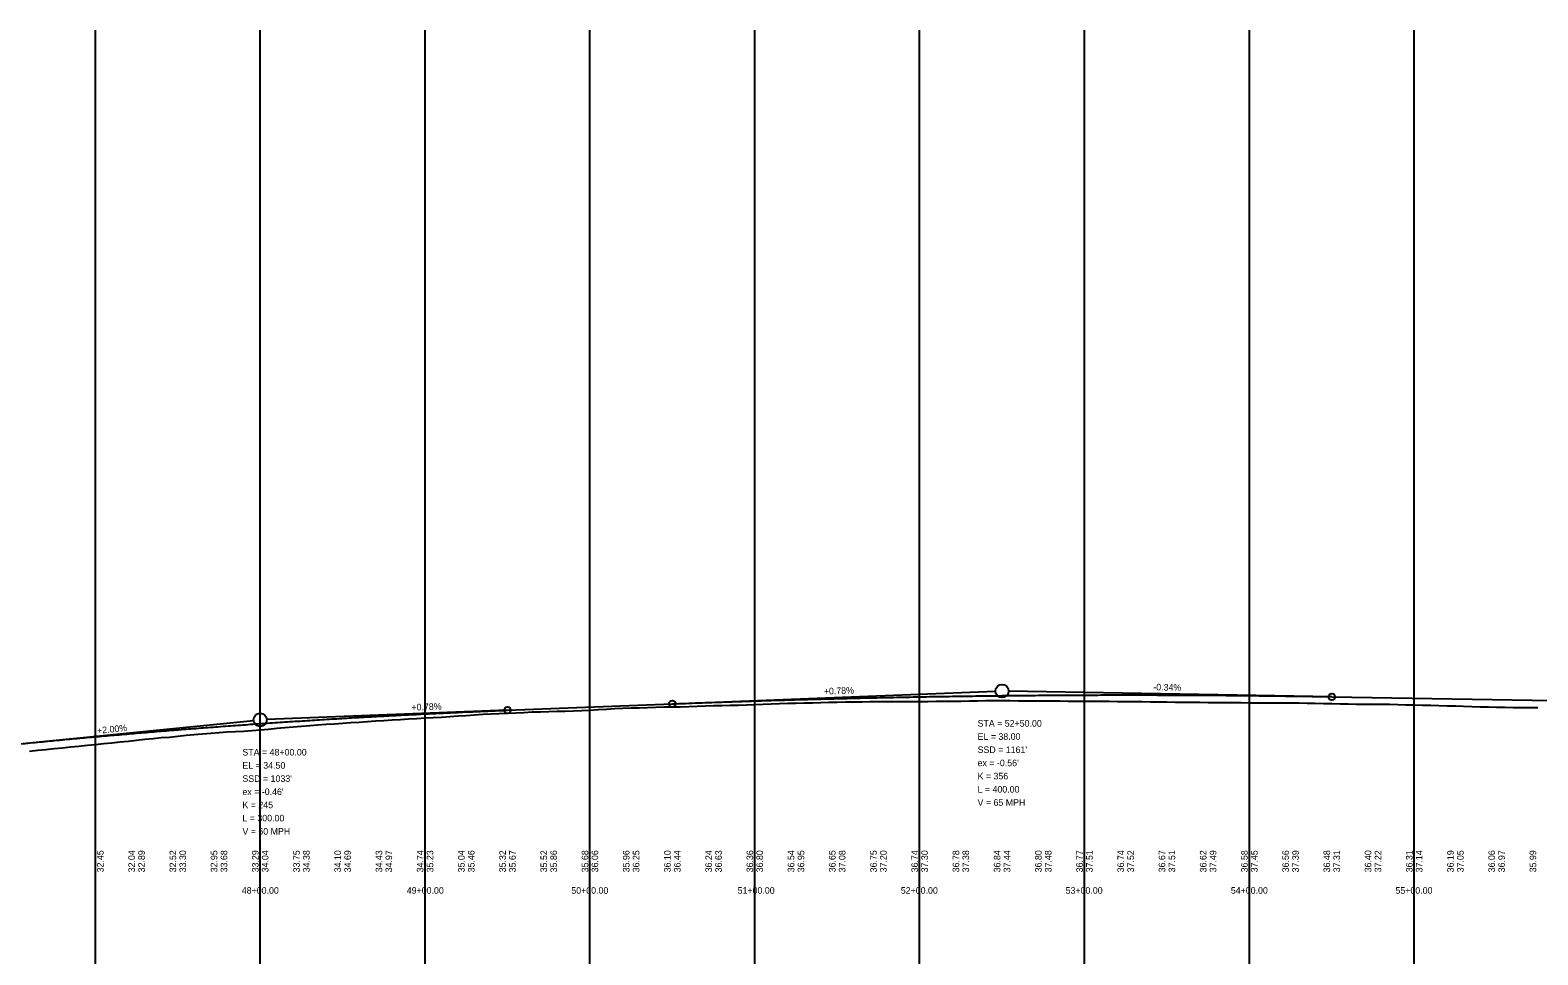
# Model space of a CAD drawing. Extents: x 3880794 to 3915434, y 287517 to 300173.
# Drawn here: x 3903812 to 3904726, y 292943 to 293504 of the extents above; entities that cross this region are included whole.
import ezdxf

# ---------------------------------------------------------------- set-up
doc = ezdxf.new("R2010")
doc.units = 0
for name, color, linetype in [('Level 1', 7, 'Continuous'), ('Level 2', 7, 'Continuous'), ('Level 30', 7, 'Continuous'), ('Level 32', 7, 'Continuous')]:
    doc.layers.add(name, color=color, linetype=linetype)

msp = doc.modelspace()

# ---------------------------------------------------------------- linework, layer by layer
at = {"layer": 'Level 1'}
for p, q in [((3903851.21, 292476.49), (3903851.21, 293504.13)), ((3903951.21, 292476.49), (3903951.21, 293504.13)), ((3904051.21, 292476.49), (3904051.21, 293504.13)), ((3904151.21, 292476.49), (3904151.21, 293504.13)), ((3904251.21, 292476.49), (3904251.21, 293504.13)), ((3904351.21, 292476.49), (3904351.21, 293504.13)), ((3904451.21, 292476.49), (3904451.21, 293504.13)), ((3904551.21, 292476.49), (3904551.21, 293504.13)), ((3904651.21, 292476.49), (3904651.21, 293504.13))]:
    msp.add_line(p, q, dxfattribs=at)
at = {"layer": 'Level 2'}
for p, q in [((3904201.21, 293095.38), (3904397.22, 293103)), ((3904601.21, 293099.71), (3904405.21, 293103.09)), ((3904601.21, 293099.71), (3904876.21, 293094.97)), ((3904101.21, 293091.49), (3903955.21, 293085.81)), ((3904101.21, 293091.49), (3904201.21, 293095.38)), ((3903801.21, 293070.66), (3903947.23, 293085.26))]:
    msp.add_line(p, q, dxfattribs=at)
for points in [[(3903811.21, 293066.74), (3903816.21, 293067.22), (3903821.21, 293067.75), (3903826.21, 293068.27), (3903831.21, 293068.77), (3903836.21, 293069.27), (3903841.21, 293069.77), (3903846.21, 293070.28), (3903851.21, 293070.8), (3903856.21, 293071.31), (3903861.21, 293071.82), (3903866.21, 293072.32), (3903871.21, 293072.83), (3903876.21, 293073.35), (3903881.21, 293073.87), (3903886.21, 293074.39), (3903891.21, 293074.9), (3903896.21, 293075.24), (3903901.21, 293075.75), (3903906.21, 293076.29), (3903911.21, 293076.79), (3903916.21, 293077.15), (3903921.21, 293077.53), (3903926.21, 293077.91), (3903931.21, 293078.39), (3903936.21, 293078.61), (3903941.21, 293078.84), (3903946.21, 293079.14), (3903951.21, 293079.62), (3903956.21, 293080.11), (3903961.21, 293080.72), (3903966.21, 293081.12), (3903971.21, 293081.51), (3903976.21, 293081.89), (3903981.21, 293082.25), (3903986.21, 293082.61), (3903991.21, 293082.96), (3903996.21, 293083.32), (3904001.21, 293083.66), (3904006.21, 293084.02), (3904011.21, 293084.35), (3904016.21, 293084.67), (3904021.21, 293084.99), (3904026.21, 293085.32), (3904031.21, 293085.65), (3904036.21, 293085.96), (3904041.21, 293086.27), (3904046.21, 293086.58), (3904051.21, 293086.88), (3904056.21, 293087.16), (3904061.21, 293087.38), (3904066.21, 293087.69), (3904071.21, 293088.03), (3904076.21, 293088.36), (3904081.21, 293088.69), (3904086.21, 293089.02), (3904091.21, 293089.26), (3904096.21, 293089.52), (3904101.21, 293089.76), (3904106.21, 293090), (3904111.21, 293090.23), (3904116.21, 293090.44), (3904121.21, 293090.6), (3904126.21, 293090.74), (3904131.21, 293090.88), (3904136.21, 293091.02), (3904141.21, 293091.17), (3904146.21, 293091.28), (3904151.21, 293091.58)], [(3904151.21, 293091.58), (3904156.21, 293092), (3904161.21, 293092.25), (3904166.21, 293092.51), (3904171.21, 293092.75), (3904176.21, 293092.95), (3904181.21, 293093.01), (3904186.21, 293093.16), (3904191.21, 293093.32), (3904196.21, 293093.49), (3904201.21, 293093.64), (3904206.21, 293093.64), (3904211.21, 293093.68), (3904216.21, 293093.93), (3904221.21, 293094.13), (3904226.21, 293094.35), (3904231.21, 293094.46), (3904236.21, 293094.53), (3904241.21, 293094.54), (3904246.21, 293094.7), (3904251.21, 293094.95), (3904256.21, 293095.19), (3904261.21, 293095.42), (3904266.21, 293095.66), (3904271.21, 293095.72), (3904276.21, 293095.83), (3904281.21, 293095.95), (3904286.21, 293096.06), (3904291.21, 293096.17), (3904296.21, 293096.32), (3904301.21, 293096.41), (3904306.21, 293096.5), (3904311.21, 293096.58), (3904316.21, 293096.66), (3904321.21, 293096.77), (3904326.21, 293096.9), (3904331.21, 293096.88), (3904336.21, 293096.86), (3904341.21, 293096.83), (3904346.21, 293096.8), (3904351.21, 293096.86), (3904356.21, 293096.9), (3904361.21, 293096.94), (3904366.21, 293096.97), (3904371.21, 293097), (3904376.21, 293097.07), (3904381.21, 293097.16), (3904386.21, 293097.23), (3904391.21, 293097.31), (3904396.21, 293097.36), (3904401.21, 293097.36), (3904406.21, 293097.33), (3904411.21, 293097.29), (3904416.21, 293097.25), (3904421.21, 293097.2), (3904426.21, 293097.15), (3904431.21, 293097.13), (3904436.21, 293097.12), (3904441.21, 293097.1), (3904446.21, 293097.07), (3904451.21, 293097.02), (3904456.21, 293097.01), (3904461.21, 293096.99), (3904466.21, 293096.98), (3904471.21, 293096.89), (3904476.21, 293096.84), (3904481.21, 293096.78), (3904486.21, 293096.72), (3904491.21, 293096.65), (3904496.21, 293096.59), (3904501.21, 293096.53), (3904506.21, 293096.47), (3904511.21, 293096.41), (3904516.21, 293096.35), (3904521.21, 293096.31), (3904526.21, 293096.26), (3904531.21, 293096.21), (3904536.21, 293096.17), (3904541.21, 293096.12), (3904546.21, 293096.11), (3904551.21, 293096.07), (3904556.21, 293096.02), (3904561.21, 293095.97), (3904566.21, 293096.01), (3904571.21, 293095.98), (3904576.21, 293095.95), (3904581.21, 293095.92), (3904586.21, 293095.89), (3904591.21, 293095.84), (3904596.21, 293095.66), (3904601.21, 293095.53), (3904606.21, 293095.41), (3904611.21, 293095.29), (3904616.21, 293095.25), (3904621.21, 293095.21), (3904626.21, 293095.17), (3904631.21, 293095.14), (3904636.21, 293095.1), (3904641.21, 293095), (3904646.21, 293094.87), (3904651.21, 293094.73)], [(3904651.21, 293094.73), (3904656.21, 293094.6), (3904661.21, 293094.53), (3904666.21, 293094.41), (3904671.21, 293094.26), (3904676.21, 293094.1), (3904681.21, 293093.95), (3904686.21, 293093.79), (3904691.21, 293093.64), (3904696.21, 293093.53), (3904701.21, 293093.43), (3904706.21, 293093.34), (3904711.21, 293093.25), (3904716.21, 293093.22), (3904721.21, 293093.16), (3904726.21, 293093.13)]]:
    msp.add_lwpolyline(points, dxfattribs=at)
for centre, radius in [((3904401.21, 293103.16), 4), ((3904601.21, 293099.71), 2), ((3904101.21, 293091.49), 2), ((3904201.21, 293095.38), 2), ((3903951.21, 293085.66), 4)]:
    msp.add_circle(centre, radius, dxfattribs=at)
for points in [[(3904201.21, 293095.38), (3904209.21, 293095.69), (3904217.21, 293095.98), (3904225.21, 293096.27), (3904233.21, 293096.55), (3904241.21, 293096.82), (3904249.21, 293097.09), (3904257.21, 293097.34), (3904265.21, 293097.58), (3904273.21, 293097.82), (3904281.21, 293098.04), (3904289.21, 293098.26), (3904297.21, 293098.47), (3904305.21, 293098.67), (3904313.21, 293098.86), (3904321.21, 293099.04), (3904329.21, 293099.21), (3904337.21, 293099.37), (3904345.21, 293099.53), (3904353.21, 293099.67), (3904361.21, 293099.81), (3904369.21, 293099.93), (3904377.21, 293100.05), (3904385.21, 293100.16), (3904393.21, 293100.26), (3904401.21, 293100.35), (3904409.21, 293100.43), (3904417.21, 293100.51), (3904425.21, 293100.57), (3904433.21, 293100.63), (3904441.21, 293100.67), (3904449.21, 293100.71), (3904457.21, 293100.74), (3904465.21, 293100.76), (3904473.21, 293100.77), (3904481.21, 293100.77), (3904489.21, 293100.76), (3904497.21, 293100.74), (3904505.21, 293100.72), (3904513.21, 293100.68), (3904521.21, 293100.64), (3904529.21, 293100.59), (3904537.21, 293100.53), (3904545.21, 293100.46), (3904553.21, 293100.38), (3904561.21, 293100.29), (3904569.21, 293100.19), (3904577.21, 293100.08), (3904585.21, 293099.97), (3904593.21, 293099.84), (3904601.21, 293099.71)], [(3903801.21, 293070.66), (3903807.21, 293071.25), (3903813.21, 293071.84), (3903819.21, 293072.42), (3903825.21, 293073), (3903831.21, 293073.57), (3903837.21, 293074.13), (3903843.21, 293074.68), (3903849.21, 293075.22), (3903855.21, 293075.76), (3903861.21, 293076.29), (3903867.21, 293076.81), (3903873.21, 293077.33), (3903879.21, 293077.84), (3903885.21, 293078.34), (3903891.21, 293078.83), (3903897.21, 293079.32), (3903903.21, 293079.8), (3903909.21, 293080.27), (3903915.21, 293080.73), (3903921.21, 293081.19), (3903927.21, 293081.64), (3903933.21, 293082.08), (3903939.21, 293082.52), (3903945.21, 293082.95), (3903951.21, 293083.37), (3903957.21, 293083.78), (3903963.21, 293084.18), (3903969.21, 293084.58), (3903975.21, 293084.97), (3903981.21, 293085.36), (3903987.21, 293085.73), (3903993.21, 293086.1), (3903999.21, 293086.46), (3904005.21, 293086.82), (3904011.21, 293087.17), (3904017.21, 293087.51), (3904023.21, 293087.84), (3904029.21, 293088.16), (3904035.21, 293088.48), (3904041.21, 293088.79), (3904047.21, 293089.09), (3904053.21, 293089.39), (3904059.21, 293089.68), (3904065.21, 293089.96), (3904071.21, 293090.23), (3904077.21, 293090.5), (3904083.21, 293090.76), (3904089.21, 293091.01), (3904095.21, 293091.25), (3904101.21, 293091.49)]]:
    msp.add_spline(points, degree=3, dxfattribs=at)

# ---------------------------------------------------------------- texts
for s, rotation, p in [('+0.78%', 2.22705, (3904293.15, 293100.96)), ('-0.34%', 359.01224, (3904492.92, 293103.58)), ('+0.78%', 2.22705, (3904043, 293091.23)), ('+2.00%', 5.71059, (3903852.45, 293077.12))]:
    msp.add_text(s, height=4, rotation=rotation, dxfattribs=at).set_placement(p)
for s, p in [('STA = 52+50.00', (3904386.35, 293081.54)), ('EL = 38.00', (3904386.35, 293073.54)), ('STA = 48+00.00', (3903940.41, 293064.04)), ("SSD = 1161'", (3904386.35, 293065.54)), ('EL = 34.50', (3903940.41, 293056.04)), ("ex = -0.56'", (3904386.35, 293057.54)), ('K = 356', (3904386.35, 293049.54)), ("SSD = 1033'", (3903940.41, 293048.04)), ('L = 400.00', (3904386.35, 293041.54)), ("ex = -0.46'", (3903940.41, 293040.04)), ('K = 245', (3903940.41, 293032.04)), ('V = 65 MPH', (3904386.35, 293033.54)), ('L = 300.00', (3903940.41, 293024.04)), ('V = 60 MPH', (3903940.41, 293016.04))]:
    msp.add_text(s, height=4, dxfattribs=at).set_placement(p)
at = {"layer": 'Level 30'}
for s, p in [('48+00.00', (3903940.03, 292980.16)), ('48+00.00', (3903940.03, 292980.16)), ('49+00.00', (3904040.1, 292980.16)), ('49+00.00', (3904040.1, 292980.16)), ('50+00.00', (3904139.91, 292980.16)), ('50+00.00', (3904139.91, 292980.16)), ('51+00.00', (3904240.79, 292980.16)), ('51+00.00', (3904240.79, 292980.16)), ('52+00.00', (3904339.78, 292980.16)), ('52+00.00', (3904339.78, 292980.16)), ('53+00.00', (3904439.75, 292980.16)), ('53+00.00', (3904439.75, 292980.16)), ('54+00.00', (3904539.97, 292980.16)), ('54+00.00', (3904539.97, 292980.16)), ('55+00.00', (3904639.84, 292980.16)), ('55+00.00', (3904639.84, 292980.16))]:
    msp.add_text(s, height=4, dxfattribs=at).set_placement(p)
at = {"layer": 'Level 32'}
for s, p in [('32.45', (3903856.21, 292993.16)), ('32.04', (3903875.21, 292993.16)), ('32.89', (3903881.21, 292993.16)), ('32.52', (3903900.21, 292993.16)), ('33.30', (3903906.21, 292993.16)), ('32.95', (3903925.21, 292993.16)), ('33.68', (3903931.21, 292993.16)), ('33.29', (3903950.21, 292993.16)), ('34.04', (3903956.21, 292993.16)), ('33.75', (3903975.21, 292993.16)), ('34.38', (3903981.21, 292993.16)), ('34.10', (3904000.21, 292993.16)), ('34.69', (3904006.21, 292993.16)), ('34.43', (3904025.21, 292993.16)), ('34.97', (3904031.21, 292993.16)), ('34.74', (3904050.21, 292993.16)), ('35.23', (3904056.21, 292993.16)), ('35.04', (3904075.21, 292993.16)), ('35.46', (3904081.21, 292993.16)), ('35.32', (3904100.21, 292993.16)), ('35.67', (3904106.21, 292993.16)), ('35.52', (3904125.21, 292993.16)), ('35.86', (3904131.21, 292993.16)), ('35.68', (3904150.21, 292993.16)), ('36.06', (3904156.21, 292993.16)), ('35.96', (3904175.21, 292993.16)), ('36.25', (3904181.21, 292993.16)), ('36.10', (3904200.21, 292993.16)), ('36.44', (3904206.21, 292993.16)), ('36.24', (3904225.21, 292993.16)), ('36.63', (3904231.21, 292993.16)), ('36.36', (3904250.21, 292993.16)), ('36.80', (3904256.21, 292993.16)), ('36.54', (3904275.21, 292993.16)), ('36.95', (3904281.21, 292993.16)), ('36.65', (3904300.21, 292993.16)), ('37.08', (3904306.21, 292993.16)), ('36.75', (3904325.21, 292993.16)), ('37.20', (3904331.21, 292993.16)), ('36.74', (3904350.21, 292993.16)), ('37.30', (3904356.21, 292993.16)), ('36.78', (3904375.21, 292993.16)), ('37.38', (3904381.21, 292993.16)), ('36.84', (3904400.21, 292993.16)), ('37.44', (3904406.21, 292993.16)), ('36.80', (3904425.21, 292993.16)), ('37.48', (3904431.21, 292993.16)), ('36.77', (3904450.21, 292993.16)), ('37.51', (3904456.21, 292993.16)), ('36.74', (3904475.21, 292993.16)), ('37.52', (3904481.21, 292993.16)), ('36.67', (3904500.21, 292993.16)), ('37.51', (3904506.21, 292993.16)), ('36.62', (3904525.21, 292993.16)), ('37.49', (3904531.21, 292993.16)), ('36.58', (3904550.21, 292993.16)), ('37.45', (3904556.21, 292993.16)), ('36.56', (3904575.21, 292993.16)), ('37.39', (3904581.21, 292993.16)), ('36.48', (3904600.21, 292993.16)), ('37.31', (3904606.21, 292993.16)), ('36.40', (3904625.21, 292993.16)), ('37.22', (3904631.21, 292993.16)), ('36.31', (3904650.21, 292993.16)), ('37.14', (3904656.21, 292993.16)), ('36.19', (3904675.21, 292993.16)), ('37.05', (3904681.21, 292993.16)), ('36.06', (3904700.21, 292993.16)), ('36.97', (3904706.21, 292993.16)), ('35.99', (3904725.21, 292993.16))]:
    msp.add_text(s, height=4, rotation=90, dxfattribs=at).set_placement(p)

doc.saveas('drawing.dxf')
